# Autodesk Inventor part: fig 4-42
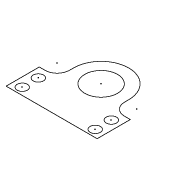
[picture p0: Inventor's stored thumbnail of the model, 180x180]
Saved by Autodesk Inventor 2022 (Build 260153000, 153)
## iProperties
Created: 2004-05
Part Number: fig 4-42
Document SubType Name: Modeling
Designer: CADCIM Technologies
Manufacturer: Standard
Standards Organization: Custom
Density: 1 g/cm^3
Material: Generic
Appearance: Default
Author: CADCIM Technologies
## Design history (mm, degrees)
sketch "Sketch1"
  geometry: L1 (41.331, 50.432)-(41.331, 48.38); L2 (35.331, 42.38)-(32.489, 42.38); L3 (32.489, 42.38)-(32.489, 26.047); L4 (68.481, 50.432)-(68.481, 48.38); L5 (74.481, 42.38)-(77.323, 42.38); L6 (77.323, 42.38)-(77.323, 26.047); L7 (32.489, 26.047)-(77.323, 26.047); C1 r 8.09 at (54.906, 50.432); C2 r 2.534 at (36.931, 29.558); C3 r 2.534 at (36.931, 37.474); C4 r 2.534 at (72.881, 37.474); C5 r 2.534 at (72.881, 29.558); A1 r 13.575 centre (54.906, 50.432) between (68.481, 50.432) and (41.331, 50.432); A2 r 6 centre (35.331, 48.38) between (35.331, 42.38) and (41.331, 48.38); A3 r 6 centre (74.481, 48.38) between (68.481, 48.38) and (74.481, 42.38)
  constraints: 14 end point, 8 centre point, 6 point on circle, 6 tangent, 3 equal length, 2 horizontal, 2 perpendicular, 1 coincident, 1 equal radius, 1 parallel, 1 vertical
